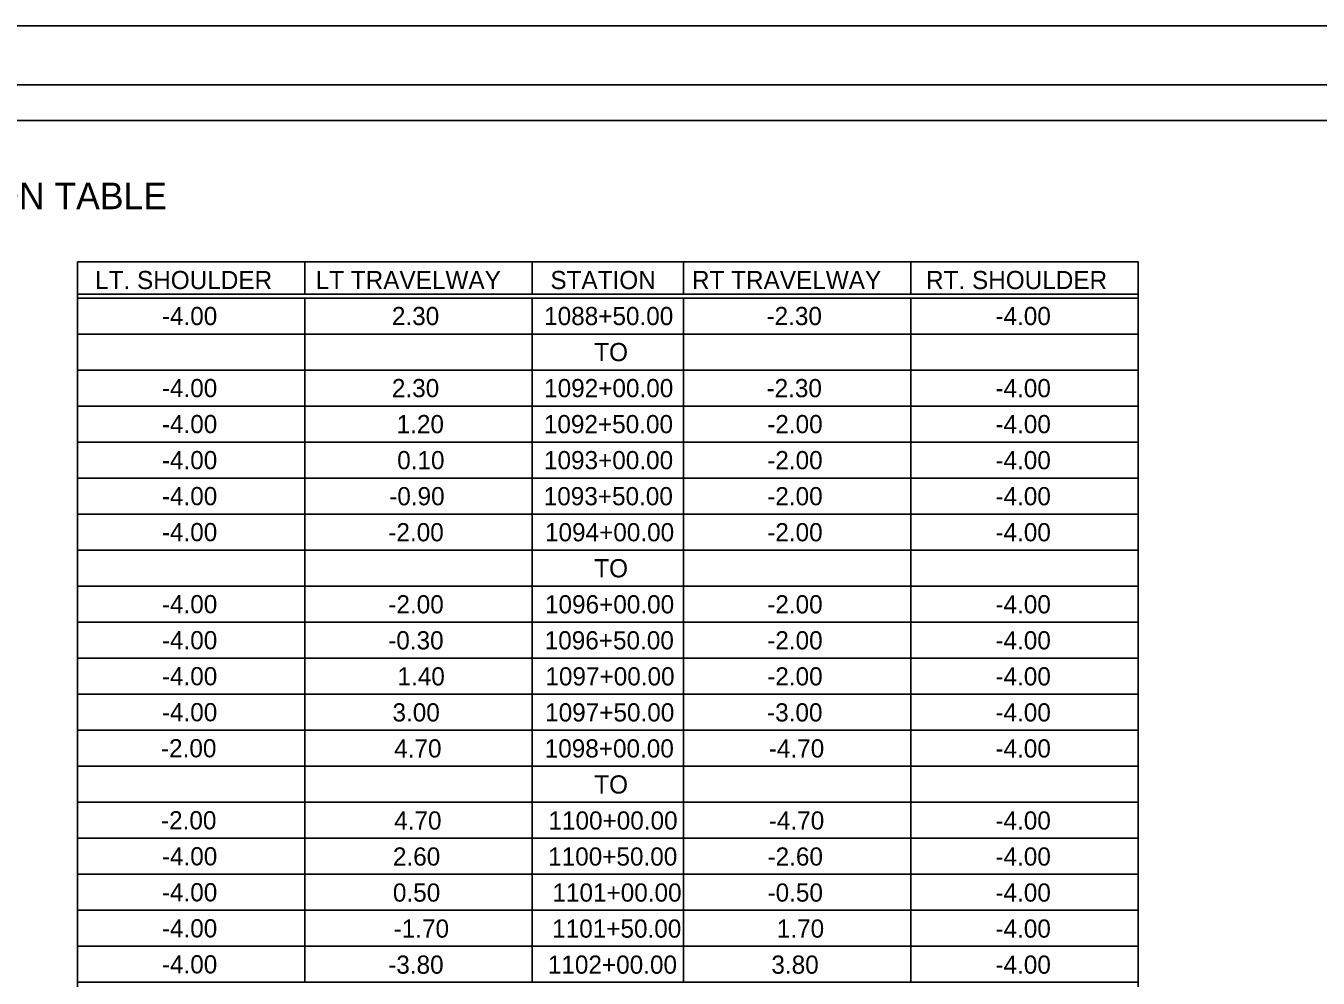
# Model space of a CAD drawing. Extents: x 1026502 to 1027102, y 781811 to 782040.
# Drawn here: x 1026686.67 to 1026720.77, y 781917.29 to 781942.42 of the extents above; entities that cross this region are included whole.
import ezdxf

# ---------------------------------------------------------------- set-up
doc = ezdxf.new("R2010")
doc.units = 0
for name, color, linetype in [('ANNOTATION', 7, 'Continuous'), ('BORDER', 7, 'Continuous'), ('DIMENSIONS', 7, 'Continuous'), ('JUNK', 7, 'Continuous'), ('PLOT BOUNDARY', 7, 'Continuous')]:
    doc.layers.add(name, color=color, linetype=linetype)

msp = doc.modelspace()

# ---------------------------------------------------------------- linework, layer by layer
at = {"layer": 'ANNOTATION'}
msp.add_lwpolyline([(1026688.027, 781936.19), (1026716.027, 781936.19), (1026716.027, 781882.017), (1026688.027, 781882.017)], close=True, dxfattribs=at)
at = {"layer": 'BORDER'}
for p, q in [((1026753.357, 781940.868), (1026625.357, 781940.868)), ((1026688.027, 781936.19), (1026688.027, 781935.345)), ((1026691.027, 781935.239), (1026688.027, 781935.239)), ((1026688.027, 781935.239), (1026688.027, 781934.289)), ((1026716.027, 781935.239), (1026716.027, 781934.289)), ((1026691.027, 781934.289), (1026688.027, 781934.289)), ((1026691.027, 781934.289), (1026688.027, 781934.289)), ((1026691.027, 781933.338), (1026688.027, 781933.338)), ((1026691.027, 781933.338), (1026688.027, 781933.338)), ((1026691.027, 781933.338), (1026694.027, 781933.338)), ((1026691.027, 781932.388), (1026688.027, 781932.388)), ((1026691.027, 781932.388), (1026688.027, 781932.388)), ((1026691.027, 781932.388), (1026694.027, 781932.388)), ((1026691.027, 781931.438), (1026688.027, 781931.438)), ((1026691.027, 781931.438), (1026688.027, 781931.438)), ((1026691.027, 781931.438), (1026694.027, 781931.438)), ((1026691.027, 781930.487), (1026688.027, 781930.487)), ((1026691.027, 781930.487), (1026688.027, 781930.487)), ((1026691.027, 781930.487), (1026694.027, 781930.487)), ((1026691.027, 781929.537), (1026688.027, 781929.537)), ((1026691.027, 781929.537), (1026688.027, 781929.537)), ((1026691.027, 781929.537), (1026694.027, 781929.537)), ((1026691.027, 781928.586), (1026688.027, 781928.586)), ((1026691.027, 781928.586), (1026688.027, 781928.586)), ((1026691.027, 781928.586), (1026694.027, 781928.586)), ((1026691.027, 781927.636), (1026688.027, 781927.636)), ((1026691.027, 781927.636), (1026688.027, 781927.636)), ((1026691.027, 781927.636), (1026694.027, 781927.636)), ((1026691.027, 781926.686), (1026688.027, 781926.686)), ((1026691.027, 781926.686), (1026688.027, 781926.686)), ((1026691.027, 781926.686), (1026694.027, 781926.686)), ((1026691.027, 781925.735), (1026688.027, 781925.735)), ((1026691.027, 781925.735), (1026688.027, 781925.735)), ((1026691.027, 781925.735), (1026694.027, 781925.735)), ((1026691.027, 781924.785), (1026688.027, 781924.785)), ((1026691.027, 781924.785), (1026688.027, 781924.785)), ((1026691.027, 781924.785), (1026694.027, 781924.785)), ((1026691.027, 781923.834), (1026688.027, 781923.834)), ((1026691.027, 781923.834), (1026688.027, 781923.834)), ((1026691.027, 781923.834), (1026694.027, 781923.834)), ((1026691.027, 781922.884), (1026688.027, 781922.884)), ((1026691.027, 781922.884), (1026688.027, 781922.884)), ((1026691.027, 781922.884), (1026694.027, 781922.884)), ((1026691.027, 781921.934), (1026688.027, 781921.934)), ((1026691.027, 781921.934), (1026688.027, 781921.934)), ((1026691.027, 781921.934), (1026694.027, 781921.934)), ((1026691.027, 781920.983), (1026688.027, 781920.983)), ((1026691.027, 781920.983), (1026688.027, 781920.983)), ((1026691.027, 781920.983), (1026694.027, 781920.983)), ((1026691.027, 781920.033), (1026688.027, 781920.033)), ((1026691.027, 781920.033), (1026688.027, 781920.033)), ((1026691.027, 781920.033), (1026694.027, 781920.033)), ((1026691.027, 781919.082), (1026688.027, 781919.082)), ((1026691.027, 781919.082), (1026688.027, 781919.082)), ((1026691.027, 781919.082), (1026694.027, 781919.082)), ((1026691.027, 781918.132), (1026688.027, 781918.132)), ((1026691.027, 781918.132), (1026688.027, 781918.132)), ((1026691.027, 781918.132), (1026694.027, 781918.132))]:
    msp.add_line(p, q, dxfattribs=at)
for points in [[(1026688.027, 781936.19), (1026716.027, 781936.19), (1026716.027, 781935.239), (1026688.027, 781935.239)], [(1026688.027, 781934.289), (1026716.027, 781934.289), (1026716.027, 781933.338), (1026688.027, 781933.338)], [(1026688.027, 781933.338), (1026716.027, 781933.338), (1026716.027, 781932.388), (1026688.027, 781932.388)], [(1026688.027, 781932.388), (1026716.027, 781932.388), (1026716.027, 781931.438), (1026688.027, 781931.438)], [(1026688.027, 781931.438), (1026716.027, 781931.438), (1026716.027, 781930.487), (1026688.027, 781930.487)], [(1026688.027, 781930.487), (1026716.027, 781930.487), (1026716.027, 781929.537), (1026688.027, 781929.537)], [(1026688.027, 781929.537), (1026716.027, 781929.537), (1026716.027, 781928.586), (1026688.027, 781928.586)], [(1026688.027, 781928.586), (1026716.027, 781928.586), (1026716.027, 781927.636), (1026688.027, 781927.636)], [(1026688.027, 781927.636), (1026716.027, 781927.636), (1026716.027, 781926.686), (1026688.027, 781926.686)], [(1026688.027, 781926.686), (1026716.027, 781926.686), (1026716.027, 781925.735), (1026688.027, 781925.735)], [(1026688.027, 781925.735), (1026716.027, 781925.735), (1026716.027, 781924.785), (1026688.027, 781924.785)], [(1026688.027, 781924.785), (1026716.027, 781924.785), (1026716.027, 781923.834), (1026688.027, 781923.834)], [(1026688.027, 781923.834), (1026716.027, 781923.834), (1026716.027, 781922.884), (1026688.027, 781922.884)], [(1026688.027, 781922.884), (1026716.027, 781922.884), (1026716.027, 781921.934), (1026688.027, 781921.934)], [(1026688.027, 781921.934), (1026716.027, 781921.934), (1026716.027, 781920.983), (1026688.027, 781920.983)], [(1026688.027, 781920.983), (1026716.027, 781920.983), (1026716.027, 781920.033), (1026688.027, 781920.033)], [(1026688.027, 781920.033), (1026716.027, 781920.033), (1026716.027, 781919.082), (1026688.027, 781919.082)], [(1026688.027, 781919.082), (1026716.027, 781919.082), (1026716.027, 781918.132), (1026688.027, 781918.132)], [(1026688.027, 781918.132), (1026716.027, 781918.132), (1026716.027, 781917.182), (1026688.027, 781917.182)]]:
    msp.add_lwpolyline(points, close=True, dxfattribs=at)
for points in [[(1026688.027, 781935.345), (1026716.027, 781935.345), (1026716.027, 781936.19)], [(1026694.027, 781935.345), (1026694.027, 781936.19)], [(1026700.027, 781936.19), (1026700.027, 781935.345)], [(1026704.027, 781936.19), (1026704.027, 781935.345)], [(1026704.027, 781935.345), (1026704.027, 781936.19)], [(1026710.027, 781936.19), (1026710.027, 781935.345)], [(1026710.027, 781935.345), (1026710.027, 781936.19)], [(1026716.027, 781936.19), (1026716.027, 781935.345)], [(1026700.027, 781935.239), (1026700.027, 781934.289), (1026694.027, 781934.289), (1026694.027, 781935.239)], [(1026710.027, 781935.239), (1026710.027, 781934.289), (1026704.027, 781934.289), (1026704.027, 781935.239)], [(1026700.027, 781934.289), (1026700.027, 781933.338), (1026694.027, 781933.338), (1026694.027, 781934.289)], [(1026704.027, 781934.289), (1026704.027, 781933.338), (1026700.027, 781933.338)], [(1026710.027, 781934.289), (1026710.027, 781933.338), (1026704.027, 781933.338), (1026704.027, 781934.289)], [(1026716.027, 781934.289), (1026716.027, 781933.338), (1026710.027, 781933.338), (1026710.027, 781934.289)], [(1026700.027, 781933.338), (1026700.027, 781932.388), (1026694.027, 781932.388), (1026694.027, 781933.338)], [(1026704.027, 781933.338), (1026704.027, 781932.388), (1026700.027, 781932.388)], [(1026710.027, 781933.338), (1026710.027, 781932.388), (1026704.027, 781932.388), (1026704.027, 781933.338)], [(1026716.027, 781933.338), (1026716.027, 781932.388), (1026710.027, 781932.388), (1026710.027, 781933.338)], [(1026700.027, 781932.388), (1026700.027, 781931.438), (1026694.027, 781931.438), (1026694.027, 781932.388)], [(1026704.027, 781932.388), (1026704.027, 781931.438), (1026700.027, 781931.438)], [(1026710.027, 781932.388), (1026710.027, 781931.438), (1026704.027, 781931.438), (1026704.027, 781932.388)], [(1026716.027, 781932.388), (1026716.027, 781931.438), (1026710.027, 781931.438), (1026710.027, 781932.388)], [(1026700.027, 781931.438), (1026700.027, 781930.487), (1026694.027, 781930.487), (1026694.027, 781931.438)], [(1026704.027, 781931.438), (1026704.027, 781930.487), (1026700.027, 781930.487)], [(1026710.027, 781931.438), (1026710.027, 781930.487), (1026704.027, 781930.487), (1026704.027, 781931.438)], [(1026716.027, 781931.438), (1026716.027, 781930.487), (1026710.027, 781930.487), (1026710.027, 781931.438)], [(1026700.027, 781930.487), (1026700.027, 781929.537), (1026694.027, 781929.537), (1026694.027, 781930.487)], [(1026704.027, 781930.487), (1026704.027, 781929.537), (1026700.027, 781929.537)], [(1026710.027, 781930.487), (1026710.027, 781929.537), (1026704.027, 781929.537), (1026704.027, 781930.487)], [(1026716.027, 781930.487), (1026716.027, 781929.537), (1026710.027, 781929.537), (1026710.027, 781930.487)], [(1026700.027, 781929.537), (1026700.027, 781928.586), (1026694.027, 781928.586), (1026694.027, 781929.537)], [(1026704.027, 781929.537), (1026704.027, 781928.586), (1026700.027, 781928.586)], [(1026710.027, 781929.537), (1026710.027, 781928.586), (1026704.027, 781928.586), (1026704.027, 781929.537)], [(1026716.027, 781929.537), (1026716.027, 781928.586), (1026710.027, 781928.586), (1026710.027, 781929.537)], [(1026700.027, 781928.586), (1026700.027, 781927.636), (1026694.027, 781927.636), (1026694.027, 781928.586)], [(1026704.027, 781928.586), (1026704.027, 781927.636), (1026700.027, 781927.636)], [(1026710.027, 781928.586), (1026710.027, 781927.636), (1026704.027, 781927.636), (1026704.027, 781928.586)], [(1026716.027, 781928.586), (1026716.027, 781927.636), (1026710.027, 781927.636), (1026710.027, 781928.586)], [(1026700.027, 781927.636), (1026700.027, 781926.686), (1026694.027, 781926.686), (1026694.027, 781927.636)], [(1026704.027, 781927.636), (1026704.027, 781926.686), (1026700.027, 781926.686)], [(1026710.027, 781927.636), (1026710.027, 781926.686), (1026704.027, 781926.686), (1026704.027, 781927.636)], [(1026716.027, 781927.636), (1026716.027, 781926.686), (1026710.027, 781926.686), (1026710.027, 781927.636)], [(1026700.027, 781926.686), (1026700.027, 781925.735), (1026694.027, 781925.735), (1026694.027, 781926.686)], [(1026704.027, 781926.686), (1026704.027, 781925.735), (1026700.027, 781925.735)], [(1026710.027, 781926.686), (1026710.027, 781925.735), (1026704.027, 781925.735), (1026704.027, 781926.686)], [(1026716.027, 781926.686), (1026716.027, 781925.735), (1026710.027, 781925.735), (1026710.027, 781926.686)], [(1026700.027, 781925.735), (1026700.027, 781924.785), (1026694.027, 781924.785), (1026694.027, 781925.735)], [(1026704.027, 781925.735), (1026704.027, 781924.785), (1026700.027, 781924.785)], [(1026710.027, 781925.735), (1026710.027, 781924.785), (1026704.027, 781924.785), (1026704.027, 781925.735)], [(1026716.027, 781925.735), (1026716.027, 781924.785), (1026710.027, 781924.785), (1026710.027, 781925.735)], [(1026700.027, 781924.785), (1026700.027, 781923.834), (1026694.027, 781923.834), (1026694.027, 781924.785)], [(1026704.027, 781924.785), (1026704.027, 781923.834), (1026700.027, 781923.834)], [(1026710.027, 781924.785), (1026710.027, 781923.834), (1026704.027, 781923.834), (1026704.027, 781924.785)], [(1026716.027, 781924.785), (1026716.027, 781923.834), (1026710.027, 781923.834), (1026710.027, 781924.785)], [(1026700.027, 781923.834), (1026700.027, 781922.884), (1026694.027, 781922.884), (1026694.027, 781923.834)], [(1026704.027, 781923.834), (1026704.027, 781922.884), (1026700.027, 781922.884)], [(1026710.027, 781923.834), (1026710.027, 781922.884), (1026704.027, 781922.884), (1026704.027, 781923.834)], [(1026716.027, 781923.834), (1026716.027, 781922.884), (1026710.027, 781922.884), (1026710.027, 781923.834)], [(1026700.027, 781922.884), (1026700.027, 781921.934), (1026694.027, 781921.934), (1026694.027, 781922.884)], [(1026704.027, 781922.884), (1026704.027, 781921.934), (1026700.027, 781921.934)], [(1026710.027, 781922.884), (1026710.027, 781921.934), (1026704.027, 781921.934), (1026704.027, 781922.884)], [(1026716.027, 781922.884), (1026716.027, 781921.934), (1026710.027, 781921.934), (1026710.027, 781922.884)], [(1026700.027, 781921.934), (1026700.027, 781920.983), (1026694.027, 781920.983), (1026694.027, 781921.934)], [(1026704.027, 781921.934), (1026704.027, 781920.983), (1026700.027, 781920.983)], [(1026710.027, 781921.934), (1026710.027, 781920.983), (1026704.027, 781920.983), (1026704.027, 781921.934)], [(1026716.027, 781921.934), (1026716.027, 781920.983), (1026710.027, 781920.983), (1026710.027, 781921.934)], [(1026700.027, 781920.983), (1026700.027, 781920.033), (1026694.027, 781920.033), (1026694.027, 781920.983)], [(1026704.027, 781920.983), (1026704.027, 781920.033), (1026700.027, 781920.033)], [(1026710.027, 781920.983), (1026710.027, 781920.033), (1026704.027, 781920.033), (1026704.027, 781920.983)], [(1026716.027, 781920.983), (1026716.027, 781920.033), (1026710.027, 781920.033), (1026710.027, 781920.983)], [(1026700.027, 781920.033), (1026700.027, 781919.082), (1026694.027, 781919.082), (1026694.027, 781920.033)], [(1026704.027, 781920.033), (1026704.027, 781919.082), (1026700.027, 781919.082)], [(1026710.027, 781920.033), (1026710.027, 781919.082), (1026704.027, 781919.082), (1026704.027, 781920.033)], [(1026716.027, 781920.033), (1026716.027, 781919.082), (1026710.027, 781919.082), (1026710.027, 781920.033)], [(1026700.027, 781919.082), (1026700.027, 781918.132), (1026694.027, 781918.132), (1026694.027, 781919.082)], [(1026704.027, 781919.082), (1026704.027, 781918.132), (1026700.027, 781918.132)], [(1026710.027, 781919.082), (1026710.027, 781918.132), (1026704.027, 781918.132), (1026704.027, 781919.082)], [(1026716.027, 781919.082), (1026716.027, 781918.132), (1026710.027, 781918.132), (1026710.027, 781919.082)], [(1026700.027, 781918.132), (1026700.027, 781917.182), (1026694.027, 781917.182), (1026694.027, 781918.132)], [(1026704.027, 781918.132), (1026704.027, 781917.182), (1026700.027, 781917.182)], [(1026710.027, 781918.132), (1026710.027, 781917.182), (1026704.027, 781917.182), (1026704.027, 781918.132)], [(1026716.027, 781918.132), (1026716.027, 781917.182), (1026710.027, 781917.182), (1026710.027, 781918.132)]]:
    msp.add_lwpolyline(points, dxfattribs=at)
at = {"layer": 'JUNK'}
msp.add_lwpolyline([(1026626.458, 781939.919), (1026744.596, 781939.919), (1026744.596, 781857.651), (1026626.458, 781857.651)], close=True, dxfattribs=at)
at = {"layer": 'PLOT BOUNDARY'}
msp.add_lwpolyline([(1026618.883, 781854.421), (1026754.882, 781854.421), (1026754.882, 781942.421), (1026618.883, 781942.421)], close=True, dxfattribs=at)

# ---------------------------------------------------------------- texts
at = {"layer": 'ANNOTATION'}
msp.add_text('SUPERELEVATION TABLE', height=0.70123, dxfattribs=at).set_placement((1026678.668, 781937.583))
at = {"layer": 'DIMENSIONS'}
for s, p in [('LT. SHOULDER', (1026688.495, 781935.474)), ('LT TRAVELWAY', (1026694.318, 781935.474)), ('STATION', (1026700.511, 781935.474)), ('RT TRAVELWAY', (1026704.249, 781935.474)), ('RT. SHOULDER', (1026710.426, 781935.474)), ('-4.00', (1026690.257, 781934.524)), ('2.30', (1026696.328, 781934.524)), ('1088+50.00', (1026700.346, 781934.524)), ('-2.30', (1026706.215, 781934.524)), ('-4.00', (1026712.257, 781934.524)), ('TO', (1026701.669, 781933.573)), ('-4.00', (1026690.257, 781932.623)), ('2.30', (1026696.328, 781932.622)), ('1092+00.00', (1026700.346, 781932.622)), ('-2.30', (1026706.215, 781932.622)), ('-4.00', (1026712.257, 781932.622)), ('-4.00', (1026690.257, 781931.673)), ('1.20', (1026696.453, 781931.672)), ('1092+50.00', (1026700.339, 781931.672)), ('-2.00', (1026706.234, 781931.672)), ('-4.00', (1026712.257, 781931.672)), ('-4.00', (1026690.257, 781930.722)), ('0.10', (1026696.468, 781930.721)), ('1093+00.00', (1026700.342, 781930.721)), ('-2.00', (1026706.234, 781930.721)), ('-4.00', (1026712.257, 781930.721)), ('-4.00', (1026690.257, 781929.772)), ('-0.90', (1026696.257, 781929.77)), ('1093+50.00', (1026700.335, 781929.77)), ('-2.00', (1026706.234, 781929.77)), ('-4.00', (1026712.257, 781929.77)), ('-4.00', (1026690.257, 781928.822)), ('-2.00', (1026696.234, 781928.819)), ('1094+00.00', (1026700.369, 781928.819)), ('-2.00', (1026706.234, 781928.819)), ('-4.00', (1026712.257, 781928.819)), ('TO', (1026701.669, 781927.868)), ('-4.00', (1026690.257, 781926.921)), ('-2.00', (1026696.234, 781926.917)), ('1096+00.00', (1026700.369, 781926.917)), ('-2.00', (1026706.234, 781926.917)), ('-4.00', (1026712.257, 781926.917)), ('-4.00', (1026690.257, 781925.97)), ('-0.30', (1026696.23, 781925.967)), ('1096+50.00', (1026700.361, 781925.967)), ('-2.00', (1026706.234, 781925.967)), ('-4.00', (1026712.257, 781925.967)), ('-4.00', (1026690.257, 781925.02)), ('1.40', (1026696.476, 781925.016)), ('1097+00.00', (1026700.38, 781925.016)), ('-2.00', (1026706.234, 781925.016)), ('-4.00', (1026712.257, 781925.016)), ('-4.00', (1026690.257, 781924.07)), ('3.00', (1026696.344, 781924.065)), ('1097+50.00', (1026700.373, 781924.065)), ('-3.00', (1026706.23, 781924.065)), ('-4.00', (1026712.257, 781924.065)), ('-2.00', (1026690.234, 781923.119)), ('4.70', (1026696.389, 781923.114)), ('1098+00.00', (1026700.361, 781923.114)), ('-4.70', (1026706.276, 781923.114)), ('-4.00', (1026712.257, 781923.114)), ('TO', (1026701.669, 781922.163)), ('-2.00', (1026690.234, 781921.218)), ('4.70', (1026696.389, 781921.212)), ('1100+00.00', (1026700.46, 781921.212)), ('-4.70', (1026706.276, 781921.212)), ('-4.00', (1026712.257, 781921.212)), ('-4.00', (1026690.257, 781920.268)), ('2.60', (1026696.355, 781920.262)), ('1100+50.00', (1026700.452, 781920.262)), ('-2.60', (1026706.242, 781920.262)), ('-4.00', (1026712.257, 781920.262)), ('-4.00', (1026690.257, 781919.318)), ('0.50', (1026696.355, 781919.311)), ('1101+00.00', (1026700.565, 781919.311)), ('-0.50', (1026706.242, 781919.311)), ('-4.00', (1026712.257, 781919.311)), ('-4.00', (1026690.257, 781918.367)), ('-1.70', (1026696.374, 781918.36)), ('1101+50.00', (1026700.558, 781918.36)), ('1.70', (1026706.487, 781918.36)), ('-4.00', (1026712.257, 781918.36)), ('-4.00', (1026690.257, 781917.417)), ('-3.80', (1026696.23, 781917.409)), ('1102+00.00', (1026700.444, 781917.409)), ('3.80', (1026706.344, 781917.409)), ('-4.00', (1026712.257, 781917.409))]:
    msp.add_text(s, height=0.48, dxfattribs=at).set_placement(p)

doc.saveas('drawing.dxf')
